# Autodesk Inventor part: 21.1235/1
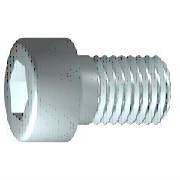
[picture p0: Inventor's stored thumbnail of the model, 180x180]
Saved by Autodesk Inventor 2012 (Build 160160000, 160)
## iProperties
Created: 2006-02
Part Number: 21.1235/1
Material: Steel, Mild
Description: M5 x 16 SHCS
Document SubType Name: Modeling
Standard: DIN 7984
Designer: Andy Moles
Standards Organization: DIN
Language: en-US
Size Designation: M5 x 16
Categories: <MemberInstance><Categories><Category DisplayName="Fasteners" InternalName="e4da775c-781d-43d5-af7c-5136215cf5a6" Mnemonic="FSTN"><Category DisplayName="Bolts"
Density: 7.86 g/cm^3
Mass: 3.81606 g
Surface Area: 4.77789 cm^2
Volume: 0.485504 cm^3
Vendor: S
Stock Number: M5 x 16 SHCS SS
Author: Andy Moles
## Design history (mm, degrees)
body "Solid1"
workplane "Work Plane1"
revolve "Body" stored, may be unused: angle "d10" = 90 deg
sketch "Sketch2"
  geometry: L1 (0, -5.95)-(0, 5.95) reference; L2 (-5.95, 0)-(5.95, 0) reference; L3 (1.732, 0)-(0.866, -1.5); L4 (0.866, -1.5)-(-0.866, -1.5); L5 (-0.866, -1.5)-(-1.732, 0); L6 (-1.732, 0)-(-0.866, 1.5); L7 (-0.866, 1.5)-(0.866, 1.5); L8 (0.866, 1.5)-(1.732, 0); 2 further points
  constraints: 12 end point, 1 coincident, 1 horizontal alignment, 1 point on line, 12 other
extrude "Slot" join sketch "Sketch2" stored distance "d11" = 10; taper "d12" = 0 deg
fillet "Fillet1" dims "d17" = 0.5 (= RR)
feature "Thread" dims "d13" = 16, "d14" = 0
chamfer "Chamfer1" distance "d15" = 0.49076 (= -0.5 x SPD + 0.5 x GD); stored, may be unused: second distance "d16" = 0.49076 (= GUL), angle "d27" = 45 deg
sketch "Sketch1"
  geometry: L1 (0.2, 0)-(16, 0); L2 (16, 0)-(16, 2.5); L3 (16, 2.5)-(2.4, 2.5); L4 (2.4, 2.5)-(1.909, 2.5); L5 (1.909, 2.5)-(0, 2.5); L6 (0, 2.5)-(0, 4.25); L7 (0, 4.25)-(-3.5, 4.25); L8 (-3.5, 4.25)-(-3.5, 1.732); L9 (-3.5, 1.732)-(-0.8, 1.732); L10 (-0.8, 1.732)-(0.2, 0); L11 (-7.4, 0)-(19.9, 0) reference; L12 (0, -0.85)-(0, 5.1) reference; L13 (2.4, 2.5)-(0, 2.5)
  constraints: 22 end point, 6 parallel, 2 collinear, 2 perpendicular, 1 horizontal, 1 point on line
  dimensions: "d1" = 13.6 distance from line of L3.end L2 (= GEL); "d2" = 0.49086 distance of L4.end L3.end (computed from GAL); "d3" = 3.5 distance between parallel lines of L8 L6 (= KOH); "d4" = 2.7 distance of L8.end L9.end (= INTI); "d5" = 60 deg angle of L10 L1; "d6" = 5 diameter of L3 L1 (= GD); "d7" = 5 diameter of L5 L1 (= BDM); "d8" = 3.4641 diameter of L9 L1 (= 1.1547 x SW); "d9" = 8.5 diameter of L7 L1 (= KOD); "d26" = 16 distance between parallel lines of L12 L2 (= NLG)
other parameters: "GD" = 5 (= NND) [user parameter; used in 2 equation terms], "NLG" = 16 [user parameter; used in 1 equation term], "GEL" = 13.6 [user parameter; used in 1 equation term], "KOD" = 8.5 [user parameter; used in 1 equation term], "KOH" = 3.5 [user parameter; used in 1 equation term], "INTI" = 2.7 [user parameter; used in 1 equation term], "GAL" = 0.49076 (= 0.61345 x PTC) [user parameter; used in 1 equation term], "GUL" = 0.49076 (= 0.61345 x PTC) [user parameter; used in 1 equation term], "BDM" = 5 (= NND) [user parameter; used in 1 equation term], "SW" = 3 [user parameter; used in 2 equation terms], "RR" = 0.5 [user parameter; used in 1 equation term], "SPD" = 4.01848 (= NND - 1.2269 x PTC) [user parameter; used in 1 equation term], "d19" = 0, "d28" = 0, "d29" = 0, "TOA" = 30 deg [user parameter], "GD1" = 4.01848 (= THREADDIA - 1.2269 x PTC) [user parameter], "THREADDIA" = 5 [user parameter; used in 1 equation term], "FAWI" = 45 deg [user parameter], "ANG" = 120 deg [user parameter], "TPU" = 12.5 (computed from PTC) [user parameter], "PTC" = 0.8 [user parameter; used in 5 equation terms], "NND" = 5 [user parameter; used in 3 equation terms], "E0" = 3.465 (= 1.155 x SW) [user parameter]
